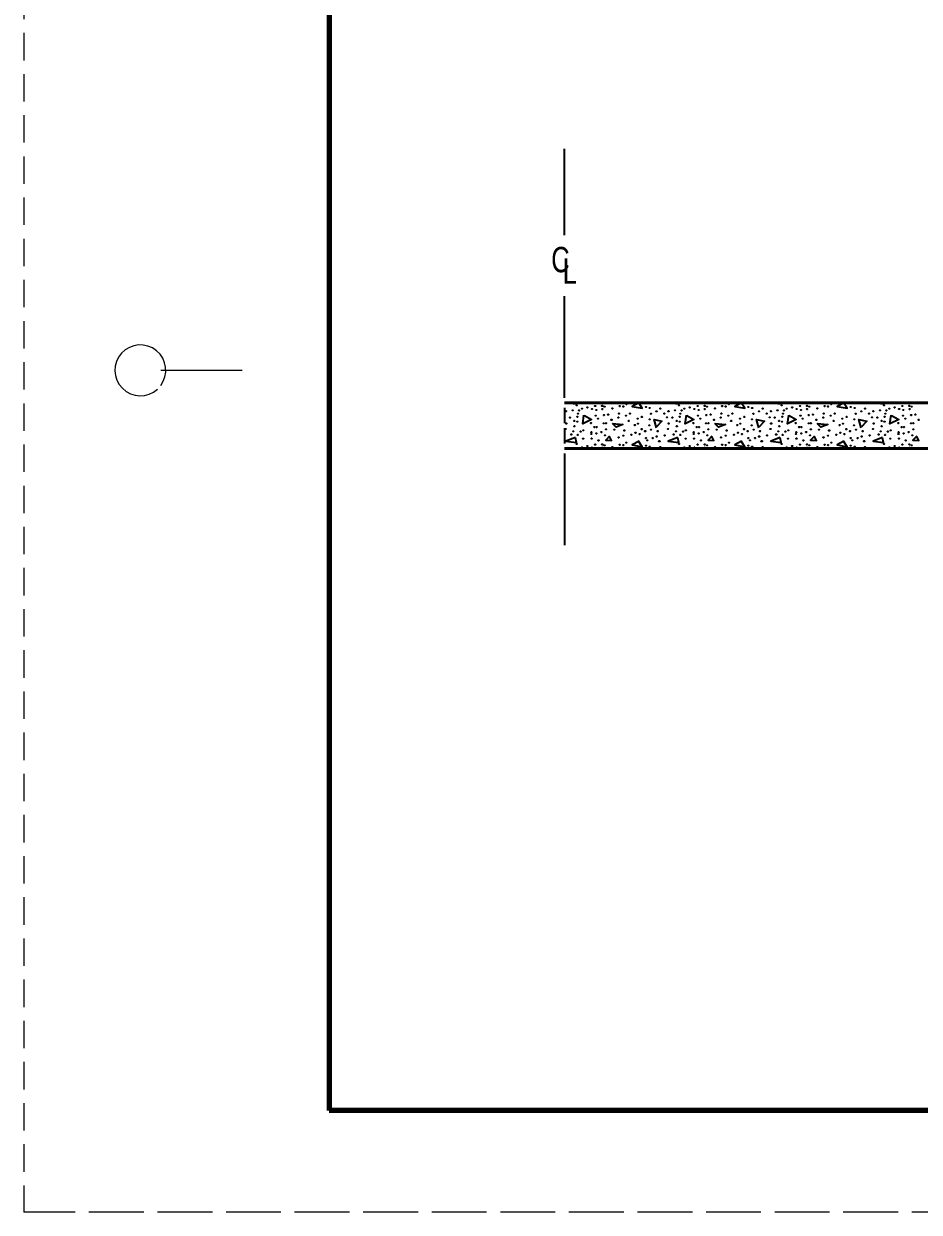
# Model space of a CAD drawing. Extents: x -54 to 626, y -41 to 399.
# Drawn here: x -54.4 to 33.7, y -41.3 to 75.6 of the extents above; entities that cross this region are included whole.
import ezdxf

# ---------------------------------------------------------------- set-up
doc = ezdxf.new("R2010")
doc.units = 0
doc.header["$LTSCALE"] = 0.9
doc.linetypes.add('LONG_DASHED', pattern=[7.5, 6, -1.5])
doc.linetypes.add('MEDIUM_DASHED', pattern=[4.5, 3, -1.5])
doc.layers.add('1', color=7, linetype='Continuous', lineweight=35)
doc.layers.add('61', color=7, linetype='Continuous', lineweight=35)

msp = doc.modelspace()

# ---------------------------------------------------------------- linework, layer by layer
at = {"layer": '1', "linetype": 'MEDIUM_DASHED', "lineweight": 13}
msp.add_line((-54.3422, 398.7039), (-54.4022, -41.3361), dxfattribs=at)
at = {"layer": '1'}
for p, q in [((-1.1842, 54.8083), (-1.1842, 63.3083)), ((-1.1842, 38.8083), (-1.1842, 48.8083)), ((-1.1842, 37.8083), (-1.1842, 36.3083)), ((-1.1842, 35.8083), (-1.1842, 34.3083)), ((-1.1842, 33.3083), (-1.1842, 24.3082))]:
    msp.add_line(p, q, dxfattribs=at)
at = {"layer": '1', "lineweight": 53}
msp.add_line((93.8158, 33.8083), (-1.1842, 33.8083), dxfattribs=at)
msp.add_lwpolyline([(-1.1842, 38.3083), (93.8158, 38.3083), (93.8158, 36.3054), (93.8158, 33.8083)], dxfattribs=at)
at = {"layer": '1'}
for points in [[(-0.9528, 38.3083), (-0.0082, 38.1992), (-0.0318, 38.3083)], [(9.1272, 38.3083), (10.0718, 38.1992), (10.0482, 38.3083)], [(19.2072, 38.3083), (20.1518, 38.1992), (20.1282, 38.3083)], [(26.2917, 38.3083), (25.6518, 37.9592), (26.6318, 37.7792), (26.2918, 38.3083)], [(29.2872, 38.3083), (30.2318, 38.1992), (30.2082, 38.3083)], [(0.7718, 37.0592), (1.4718, 36.6593), (0.6118, 36.2392), (0.7318, 37.0793)], [(7.8718, 35.8592), (7.6318, 36.6593), (8.4118, 36.4992), (7.8518, 35.8993)], [(10.8518, 37.0592), (11.5518, 36.6593), (10.6918, 36.2392), (10.8118, 37.0793)], [(17.9518, 35.8592), (17.7118, 36.6593), (18.4918, 36.4992), (17.9318, 35.8993)], [(20.9318, 37.0592), (21.6318, 36.6593), (20.7718, 36.2392), (20.8918, 37.0793)], [(28.0318, 35.8592), (27.7918, 36.6593), (28.5718, 36.4992), (28.0118, 35.8993)], [(31.0118, 37.0592), (31.7118, 36.6593), (30.8518, 36.2392), (30.9718, 37.0793)], [(-0.1082, 34.8993), (-1.0482, 34.5192), (-0.0082, 34.3993), (-0.1082, 34.8592)], [(3.2518, 35.0392), (2.8718, 34.6392), (3.4518, 34.5992), (3.2518, 34.9992)], [(6.1518, 34.5192), (5.4918, 34.1593), (6.4718, 33.9793), (6.1118, 34.5392)], [(9.9718, 34.8993), (9.0318, 34.5192), (10.0718, 34.3993), (9.9718, 34.8592)], [(13.3318, 35.0392), (12.9518, 34.6392), (13.5318, 34.5992), (13.3318, 34.9992)], [(16.2318, 34.5192), (15.5718, 34.1593), (16.5518, 33.9793), (16.1918, 34.5392)], [(20.0518, 34.8993), (19.1118, 34.5192), (20.1518, 34.3993), (20.0518, 34.8592)], [(23.4118, 35.0392), (23.0318, 34.6392), (23.6118, 34.5992), (23.4118, 34.9992)], [(26.3118, 34.5192), (25.6518, 34.1593), (26.6318, 33.9793), (26.2718, 34.5392)], [(30.1318, 34.8993), (29.1918, 34.5192), (30.2318, 34.3993), (30.1318, 34.8592)], [(33.4918, 35.0392), (33.1118, 34.6392), (33.6918, 34.5992), (33.4918, 34.9992)]]:
    msp.add_lwpolyline(points, dxfattribs=at)
for points in [[(6.1317, 38.3083), (5.4918, 37.9592), (6.4718, 37.7792)], [(16.2117, 38.3083), (15.5718, 37.9592), (16.5518, 37.7792)], [(3.5318, 36.2792), (4.5718, 36.1593), (3.8918, 35.9192)], [(13.6118, 36.2792), (14.6518, 36.1593), (13.9718, 35.9192)], [(23.6918, 36.2792), (24.7318, 36.1593), (24.0518, 35.9192)]]:
    msp.add_lwpolyline(points, close=True, dxfattribs=at)
for centre in [(-1.027, 37.4779), (-0.3776, 37.5708), (0.02, 38.0612), (0.2585, 37.5575), (0.5368, 37.7298), (1.0669, 37.8491), (1.5176, 37.7033), (1.8356, 37.995), (1.9417, 37.5972), (2.5248, 38.0082), (2.538, 37.69), (2.7578, 37.9287), (3.5396, 37.7563), (4.2553, 37.9817), (4.6, 37.942), (4.918, 38.1806), (6.8265, 37.8889), (7.2108, 37.7961), (7.8735, 37.4647), (8.2446, 37.743), (9.053, 37.4779), (9.7024, 37.5708), (10.1, 38.0612), (10.3385, 37.5575), (10.6168, 37.7298), (11.1469, 37.8491), (11.5976, 37.7033), (11.9156, 37.995), (12.0217, 37.5972), (12.6048, 38.0082), (12.618, 37.69), (12.8378, 37.9287), (13.6196, 37.7563), (14.3353, 37.9817), (14.68, 37.942), (14.998, 38.1806), (16.9065, 37.8889), (17.2908, 37.7961), (17.9535, 37.4647), (18.3246, 37.743), (19.133, 37.4779), (19.7824, 37.5708), (20.18, 38.0612), (20.4185, 37.5575), (20.6968, 37.7298), (21.2269, 37.8491), (21.6776, 37.7033), (21.9956, 37.995), (22.1017, 37.5972), (22.6848, 38.0082), (22.698, 37.69), (22.9178, 37.9287), (23.6996, 37.7563), (24.4153, 37.9817), (24.76, 37.942), (25.078, 38.1806), (26.9865, 37.8889), (27.3708, 37.7961), (28.0335, 37.4647), (28.4046, 37.743), (29.213, 37.4779), (29.8624, 37.5708), (30.26, 38.0612), (30.4985, 37.5575), (30.7768, 37.7298), (31.3069, 37.8491), (31.7576, 37.7033), (32.0756, 37.995), (32.1817, 37.5972), (32.7648, 38.0082), (32.778, 37.69), (32.9978, 37.9287), (-1.0006, 36.2715), (-0.6427, 36.8548), (-0.2186, 36.5234), (0.073, 36.4571), (0.0862, 36.9344), (0.1525, 37.2393), (1.4248, 36.3113), (1.8886, 37.0405), (2.114, 36.7487), (2.6774, 36.2825), (2.6971, 37.0935), (2.9035, 36.2981), (3.1155, 37.1465), (3.4469, 36.6295), (4.1229, 36.8548), (4.1758, 37.2526), (4.865, 37.0405), (5.1433, 36.5234), (5.2626, 37.2526), (6.018, 36.7487), (6.0578, 36.2583), (6.4288, 36.9211), (7.1975, 36.6825), (7.3301, 37.226), (8.6421, 37.2526), (8.9204, 36.8814), (9.0794, 36.2715), (9.4373, 36.8548), (9.8614, 36.5234), (10.153, 36.4571), (10.1662, 36.9344), (10.2325, 37.2393), (11.5048, 36.3113), (11.9686, 37.0405), (12.194, 36.7487), (12.7574, 36.2825), (12.7771, 37.0935), (12.9835, 36.2981), (13.1955, 37.1465), (13.5269, 36.6295), (14.2029, 36.8548), (14.2558, 37.2526), (14.945, 37.0405), (15.2233, 36.5234), (15.3426, 37.2526), (16.098, 36.7487), (16.1378, 36.2583), (16.5088, 36.9211), (17.2775, 36.6825), (17.4101, 37.226), (18.7221, 37.2526), (19.0004, 36.8814), (19.1594, 36.2715), (19.5173, 36.8548), (19.9414, 36.5234), (20.233, 36.4571), (20.2462, 36.9344), (20.3125, 37.2393), (21.5848, 36.3113), (22.0486, 37.0405), (22.274, 36.7487), (22.8374, 36.2825), (22.8571, 37.0935), (23.0635, 36.2981), (23.2755, 37.1465), (23.6069, 36.6295), (24.2829, 36.8548), (24.3358, 37.2526), (25.025, 37.0405), (25.3033, 36.5234), (25.4226, 37.2526), (26.178, 36.7487), (26.2178, 36.2583), (26.5888, 36.9211), (27.3575, 36.6825), (27.4901, 37.226), (28.8021, 37.2526), (29.0804, 36.8814), (29.2394, 36.2715), (29.5973, 36.8548), (30.0214, 36.5234), (30.313, 36.4571), (30.3262, 36.9344), (30.3925, 37.2393), (31.6648, 36.3113), (32.1286, 37.0405), (32.354, 36.7487), (32.9174, 36.2825), (32.9371, 37.0935), (33.1435, 36.2981), (33.3555, 37.1465), (33.6869, 36.6295), (-1.0668, 35.728), (-0.5102, 35.1893), (-0.2981, 35.5026), (-0.2053, 36.0063), (0.126, 35.1495), (0.4043, 35.4761), (0.6826, 35.5953), (1.4513, 35.2423), (1.4646, 35.4098), (1.7562, 35.9135), (1.9549, 35.2953), (1.9814, 35.9135), (2.4453, 35.4231), (2.8108, 35.1097), (2.9035, 35.7014), (3.712, 35.6617), (4.6, 35.0699), (4.706, 35.5821), (5.4084, 35.1627), (5.7397, 36.1124), (5.806, 35.3568), (6.2035, 35.229), (6.4024, 35.7147), (6.7602, 35.5158), (7.1578, 36.0859), (7.3433, 35.6617), (7.9927, 35.5158), (8.6819, 35.0964), (9.0132, 35.728), (9.5698, 35.1893), (9.7819, 35.5026), (9.8747, 36.0063), (10.206, 35.1495), (10.4843, 35.4761), (10.7626, 35.5953), (11.5313, 35.2423), (11.5446, 35.4098), (11.8362, 35.9135), (12.0349, 35.2953), (12.0614, 35.9135), (12.5253, 35.4231), (12.8908, 35.1097), (12.9835, 35.7014), (13.792, 35.6617), (14.68, 35.0699), (14.786, 35.5821), (15.4884, 35.1627), (15.8197, 36.1124), (15.886, 35.3568), (16.2835, 35.229), (16.4824, 35.7147), (16.8402, 35.5158), (17.2378, 36.0859), (17.4233, 35.6617), (18.0727, 35.5158), (18.7619, 35.0964), (19.0932, 35.728), (19.6498, 35.1893), (19.8619, 35.5026), (19.9547, 36.0063), (20.286, 35.1495), (20.5643, 35.4761), (20.8426, 35.5953), (21.6113, 35.2423), (21.6246, 35.4098), (21.9162, 35.9135), (22.1149, 35.2953), (22.1414, 35.9135), (22.6053, 35.4231), (22.9708, 35.1097), (23.0635, 35.7014), (23.872, 35.6617), (24.76, 35.0699), (24.866, 35.5821), (25.5684, 35.1627), (25.8997, 36.1124), (25.966, 35.3568), (26.3635, 35.229), (26.5624, 35.7147), (26.9202, 35.5158), (27.3178, 36.0859), (27.5033, 35.6617), (28.1527, 35.5158), (28.8419, 35.0964), (29.1732, 35.728), (29.7298, 35.1893), (29.9419, 35.5026), (30.0347, 36.0063), (30.366, 35.1495), (30.6443, 35.4761), (30.9226, 35.5953), (31.6913, 35.2423), (31.7046, 35.4098), (31.9962, 35.9135), (32.1949, 35.2953), (32.2214, 35.9135), (32.6853, 35.4231), (33.0508, 35.1097), (33.1435, 35.7014), (0.02, 34.2612), (0.5368, 33.9298), (0.6561, 34.7783), (1.0669, 34.0491), (1.491, 34.7915), (1.5176, 33.9033), (1.8356, 34.195), (2.167, 34.606), (2.5248, 34.2082), (2.538, 33.89), (2.7578, 34.1287), (3.5396, 33.9563), (4.1493, 34.8976), (4.2553, 34.1817), (4.6, 34.142), (4.918, 34.3806), (6.8264, 34.8313), (6.8265, 34.0889), (6.9855, 34.6192), (7.2108, 33.9961), (7.5023, 34.8313), (7.9, 34.9904), (8.1253, 34.5264), (8.1783, 34.5264), (8.2446, 33.943), (10.1, 34.2612), (10.6168, 33.9298), (10.7361, 34.7783), (11.1469, 34.0491), (11.571, 34.7915), (11.5976, 33.9033), (11.9156, 34.195), (12.247, 34.606), (12.6048, 34.2082), (12.618, 33.89), (12.8378, 34.1287), (13.6196, 33.9563), (14.2293, 34.8976), (14.3353, 34.1817), (14.68, 34.142), (14.998, 34.3806), (16.9064, 34.8313), (16.9065, 34.0889), (17.0655, 34.6192), (17.2908, 33.9961), (17.5823, 34.8313), (17.98, 34.9904), (18.2053, 34.5264), (18.2583, 34.5264), (18.3246, 33.943), (20.18, 34.2612), (20.6968, 33.9298), (20.8161, 34.7783), (21.2269, 34.0491), (21.651, 34.7915), (21.6776, 33.9033), (21.9956, 34.195), (22.327, 34.606), (22.6848, 34.2082), (22.698, 33.89), (22.9178, 34.1287), (23.6996, 33.9563), (24.3093, 34.8976), (24.4153, 34.1817), (24.76, 34.142), (25.078, 34.3806), (26.9864, 34.8313), (26.9865, 34.0889), (27.1455, 34.6192), (27.3708, 33.9961), (27.6623, 34.8313), (28.06, 34.9904), (28.2853, 34.5264), (28.3383, 34.5264), (28.4046, 33.943), (30.26, 34.2612), (30.7768, 33.9298), (30.8961, 34.7783), (31.3069, 34.0491), (31.731, 34.7915), (31.7576, 33.9033), (32.0756, 34.195), (32.407, 34.606), (32.7648, 34.2082), (32.778, 33.89), (32.9978, 34.1287)]:
    msp.add_circle(centre, 0.0265, dxfattribs=at)
for centre, start, end in [((8.1253, 38.3264), 223.38683, 316.61317), ((8.1783, 38.3264), 223.38683, 316.61317), ((18.2053, 38.3264), 223.38683, 316.61317), ((18.2583, 38.3264), 223.38683, 316.61317), ((28.2853, 38.3264), 223.38683, 316.61317), ((28.3383, 38.3264), 223.38683, 316.61317), ((-1.1596, 36.8814), 201.63508, 158.36492), ((1.9417, 33.7972), 24.63166, 155.36834), ((12.0217, 33.7972), 24.63166, 155.36834), ((22.1017, 33.7972), 24.63166, 155.36834), ((32.1817, 33.7972), 24.63166, 155.36834)]:
    msp.add_arc(centre, 0.0265, start, end, dxfattribs=at)
at = {"layer": '61', "lineweight": 13}
msp.add_line((-40.9022, 41.5039), (-32.9222, 41.5039), dxfattribs=at)
at = {"layer": '61', "lineweight": 158}
msp.add_line((614.7178, -31.3361), (-24.3422, -31.3161), dxfattribs=at)
at = {"layer": '61', "linetype": 'LONG_DASHED', "lineweight": 13}
msp.add_line((625.6577, -41.3161), (-54.4022, -41.3361), dxfattribs=at)
at = {"layer": '61', "lineweight": 158}
msp.add_lwpolyline([(614.6977, 388.7039), (-24.3422, 388.7039), (-24.3422, -31.3161)], dxfattribs=at)
at = {"layer": '61', "lineweight": 13}
msp.add_arc((-42.9245, 41.5052), 2.5, 323.13009, 312.31439, dxfattribs=at)

# ---------------------------------------------------------------- texts
at = {"layer": '1', "width": 0.75}
for s, p in [('C', (-2.4865, 51.1506)), ('L', (-1.3557, 50.0193))]:
    msp.add_text(s, height=2.5, dxfattribs=at).set_placement(p)

doc.saveas('drawing.dxf')
